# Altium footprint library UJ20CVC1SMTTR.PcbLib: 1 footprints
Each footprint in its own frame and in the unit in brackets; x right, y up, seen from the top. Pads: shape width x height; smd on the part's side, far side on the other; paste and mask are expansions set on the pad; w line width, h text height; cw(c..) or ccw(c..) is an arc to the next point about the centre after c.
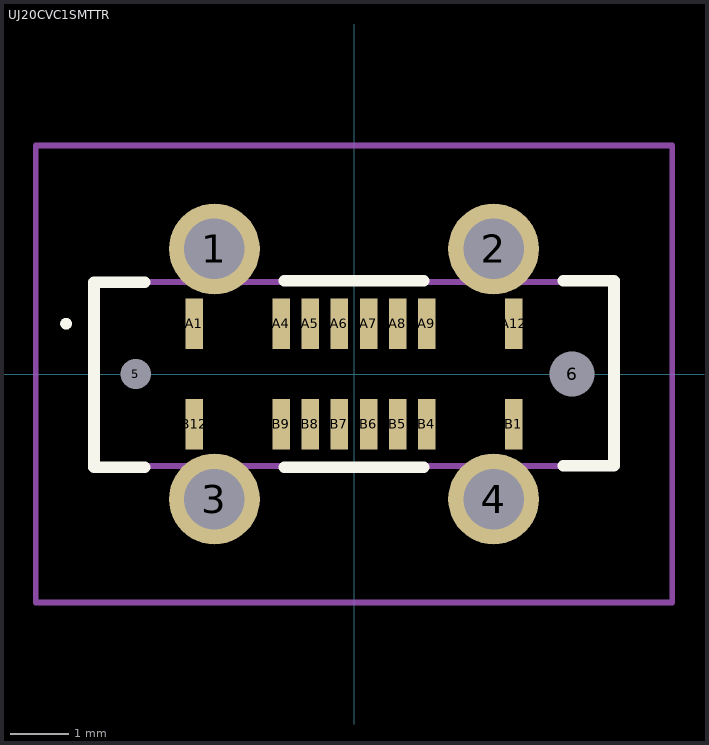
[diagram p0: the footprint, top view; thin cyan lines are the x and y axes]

## UJ20CVC1SMTTR [mm]
pads (22):
  round 1.56 hole 1.04: 1(-2.4,2.15) 2(2.4,2.15) 3(-2.4,-2.15) 4(2.4,-2.15)
  round 0.26 hole 0.52 unplated: 5(-3.75,0)
  round 0.385 hole 0.77 unplated: 6(3.75,0)
  rect 0.3x0.87 smd: A1(-2.75,0.865) A4(-1.25,0.865) A5(-0.75,0.865) A6(-0.25,0.865) A7(0.25,0.865) A8(0.75,0.865) A9(1.25,0.865) A12(2.75,0.865) B1(2.75,-0.865) B4(1.25,-0.865) B5(0.75,-0.865) B6(0.25,-0.865) B7(-0.25,-0.865) B8(-0.75,-0.865) B9(-1.25,-0.865) B12(-2.75,-0.865)
Top Overlay:
  lines w0.1: -5,0.865 cw(c-4.95,0.865) -4.9,0.865 ; -5,0.865 -5,0.865 ; -5,0.865 ccw(c-4.95,0.865) -4.9,0.865 ; -4.9,0.865 -4.9,0.865
  lines w0.2: -3.6,-1.6 -4.47,-1.6 -4.47,1.58 -3.6,1.58 ; -1.2,-1.6 1.2,-1.6 ; -1.2,1.6 1.2,1.6 ; 3.6,-1.58 4.47,-1.58 4.47,1.6 3.6,1.6
Mechanical 15:
  lines w0.1: -4.47,-1.58 4.47,-1.58 4.47,1.58 -4.47,1.58 -4.47,-1.58
Mechanical 20:
  lines w0.1: -5.47,-3.93 5.47,-3.93 5.47,3.93 -5.47,3.93 -5.47,-3.93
